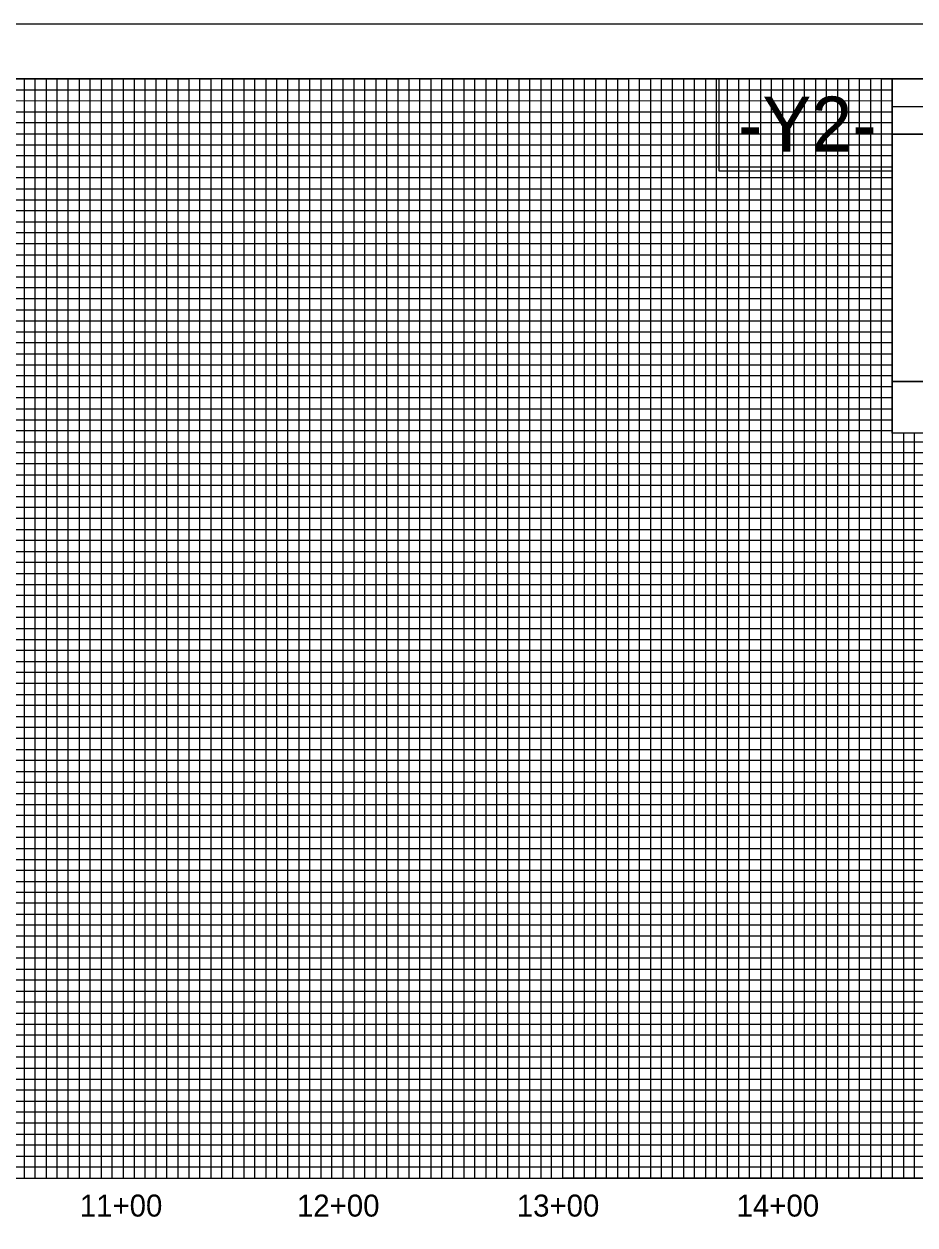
# Model space of a CAD drawing. Extents: x 505602 to 507705, y 483109 to 484209.
# Drawn here: x 506674 to 507079, y 483662 to 484209 of the extents above; entities that cross this region are included whole.
import ezdxf

# ---------------------------------------------------------------- set-up
doc = ezdxf.new("R2010")
doc.units = 0
for name, color, linetype in [('Exist Vertical Profile Vertical Axis Label', 7, 'Continuous'), ('Old_Level_1', 7, 'Continuous'), ('Prop Grid Mask', 7, 'Continuous'), ('Sheet Layout Profile Border Port 1', 7, 'Continuous'), ('Sheet Plot Border Outside CELL', 7, 'Continuous'), ('Sheet Profile CELL', 7, 'Continuous'), ('Sheet Profile Grid Major CELL', 7, 'Continuous'), ('Sheet Profile Grid Middle CELL', 7, 'Continuous'), ('Sheet Profile Grid Minor CELL', 7, 'Continuous'), ('Sheet Sticker Exception Certification CELL', 7, 'Continuous')]:
    doc.layers.add(name, color=color, linetype=linetype)

msp = doc.modelspace()

# ---------------------------------------------------------------- linework, layer by layer
at = {"layer": 'Prop Grid Mask'}
msp.add_lwpolyline([(507069.08, 484183.71), (506990.09, 484183.71), (506990.09, 484142), (507069.08, 484142)], close=True, dxfattribs=at)
at = {"layer": 'Sheet Layout Profile Border Port 1'}
msp.add_lwpolyline([(506619.08, 484183.71), (506619.08, 483683.71), (507219.08, 483683.96), (507219.08, 484022.66), (507069.08, 484022.66), (507069.03, 484183.71)], close=True, dxfattribs=at)
at = {"layer": 'Sheet Plot Border Outside CELL'}
msp.add_lwpolyline([(505602.08, 483108.71), (507286.08, 483108.71), (507286.08, 484208.71), (505602.08, 484208.71)], close=True, dxfattribs=at)
at = {"layer": 'Sheet Profile CELL'}
for p, q in [((507069.03, 484171.16), (507269.08, 484171.16)), ((505769.08, 483683.71), (507269.08, 483683.71))]:
    msp.add_line(p, q, dxfattribs=at)
for points in [[(507269.08, 484183.71), (505769.08, 484183.71), (505769.08, 483133.71), (507269.08, 483133.71)], [(507069.03, 484183.71), (507269.08, 484183.71), (507269.08, 484158.66), (507069.03, 484158.66)], [(507069.03, 484158.66), (507169.08, 484158.66), (507169.08, 484046.16), (507069.03, 484046.16)]]:
    msp.add_lwpolyline(points, close=True, dxfattribs=at)
at = {"layer": 'Sheet Profile Grid Major CELL'}
for points in [[(506669.08, 484183.71), (506719.08, 484183.71), (506719.08, 483683.71), (506769.08, 483683.71), (506769.08, 484183.71), (506819.08, 484183.71), (506819.08, 483683.71), (506869.08, 483683.71), (506869.08, 484183.71), (506919.08, 484183.71), (506919.08, 483683.71), (506969.08, 483683.71), (506969.08, 484183.71), (507019.08, 484183.71), (507019.08, 483683.71), (507069.08, 483683.71), (507069.08, 484183.71), (507095.38, 484183.71)], [(505769.08, 484133.71), (507069.08, 484133.71)], [(507069.08, 484083.71), (505769.08, 484083.71), (505769.08, 484033.71), (507069.08, 484033.71)], [(507269.08, 483983.71), (505769.08, 483983.71), (505769.08, 483933.71), (507269.08, 483933.71)], [(507269.08, 483883.71), (505769.08, 483883.71), (505769.08, 483833.71), (507269.08, 483833.71)], [(507269.08, 483783.71), (505769.08, 483783.71), (505769.08, 483783.71), (505769.08, 483733.71), (507269.08, 483733.71)]]:
    msp.add_lwpolyline(points, dxfattribs=at)
at = {"layer": 'Sheet Profile Grid Middle CELL'}
msp.add_line((505769.08, 484158.71), (507069.03, 484158.71), dxfattribs=at)
msp.add_line((505769.08, 484158.71), (507069.03, 484158.71), dxfattribs=at)
for points in [[(506644.08, 483683.71), (506694.08, 483683.71), (506694.08, 484183.71), (506744.08, 484183.71), (506744.08, 483683.71), (506794.08, 483683.71), (506794.08, 484183.71), (506844.08, 484183.71), (506844.08, 483683.71), (506894.08, 483683.71), (506894.08, 484183.71), (506944.08, 484183.71), (506944.08, 483683.71), (506994.08, 483683.71), (506994.08, 484183.71), (507044.08, 484183.71), (507044.08, 483683.71), (507094.08, 483683.71), (507094.08, 484022.66)], [(507069.08, 484108.71), (505769.08, 484108.71), (505769.08, 484058.71), (507069.08, 484058.71)], [(507269.08, 484008.71), (505769.08, 484008.71), (505769.08, 483958.71), (507094.08, 483958.71)], [(507269.08, 483908.71), (505769.08, 483908.71), (505769.08, 483858.71), (507269.08, 483858.71)], [(507269.08, 483808.71), (505769.08, 483808.71), (505769.08, 483758.71), (507269.08, 483758.71)], [(507269.08, 483708.71), (505769.08, 483708.71)]]:
    msp.add_lwpolyline(points, dxfattribs=at)
at = {"layer": 'Sheet Profile Grid Minor CELL'}
for p, q in [((505819.08, 484178.71), (507069.08, 484178.71)), ((507069.08, 484173.71), (505819.08, 484173.36)), ((505819.08, 484168.71), (507069.08, 484168.71)), ((507069.03, 484048.71), (505819.08, 484048.71)), ((507069.08, 484043.71), (505819.08, 484043.71)), ((507069.08, 484038.71), (505819.08, 484038.71)), ((505819.08, 484028.71), (507069.08, 484028.71)), ((507069.08, 484023.71), (505819.08, 484023.71)), ((505819.08, 484018.71), (507219.08, 484018.71)), ((507219.08, 483998.71), (505819.08, 483998.71)), ((505819.08, 483993.71), (507219.08, 483993.71)), ((507219.08, 483973.71), (505819.08, 483973.71)), ((505819.08, 483968.71), (507219.08, 483968.71)), ((507219.08, 483948.71), (505819.08, 483948.71)), ((505819.08, 483943.71), (507219.08, 483943.71)), ((507219.08, 483938.71), (505819.08, 483938.71)), ((505819.08, 483928.71), (507219.08, 483928.71)), ((507219.08, 483923.71), (505819.08, 483923.71)), ((505819.08, 483918.71), (507219.08, 483918.71)), ((507219.08, 483913.71), (505819.08, 483913.71)), ((505819.08, 483903.71), (507219.08, 483903.71)), ((507219.08, 483898.71), (505819.08, 483898.71)), ((505819.08, 483893.71), (507219.08, 483893.71)), ((507219.08, 483888.71), (505819.08, 483888.71)), ((505819.08, 483878.71), (507219.08, 483878.71)), ((507219.08, 483873.71), (505819.08, 483873.71)), ((505819.08, 483868.71), (507219.08, 483868.71)), ((507219.08, 483863.71), (505819.08, 483863.71)), ((505819.08, 483853.71), (507219.08, 483853.71)), ((507219.08, 483848.71), (505819.08, 483848.71)), ((505819.08, 483843.71), (507219.08, 483843.71)), ((507219.08, 483838.71), (505819.08, 483838.71)), ((505819.08, 483828.71), (507219.08, 483828.71)), ((507219.08, 483823.71), (505819.08, 483823.71)), ((505819.08, 483818.71), (507219.08, 483818.71)), ((507219.08, 483813.71), (505819.08, 483813.71)), ((505819.08, 483803.71), (507219.08, 483803.71)), ((507219.08, 483798.71), (505819.08, 483798.71)), ((507219.08, 483793.71), (505819.08, 483793.71)), ((507219.08, 483788.71), (505819.08, 483788.71)), ((505819.08, 483778.71), (507219.08, 483778.71)), ((507219.08, 483773.71), (505819.08, 483773.71)), ((505819.08, 483768.71), (507219.08, 483768.71)), ((507219.08, 483763.71), (505819.08, 483763.71)), ((505819.08, 483753.71), (507219.08, 483753.71)), ((507219.08, 483748.71), (505819.08, 483748.71)), ((505819.08, 483743.71), (507219.08, 483743.71)), ((507219.08, 483738.71), (505819.08, 483738.71)), ((505819.08, 483728.71), (507219.08, 483728.71)), ((507219.08, 483723.71), (505819.08, 483723.71)), ((505819.08, 483718.71), (507219.08, 483718.71)), ((507219.08, 483713.71), (505819.08, 483713.71)), ((505819.08, 483703.71), (507219.08, 483703.71)), ((507219.08, 483698.71), (505819.08, 483698.71)), ((505819.08, 483693.71), (507219.08, 483693.71))]:
    msp.add_line(p, q, dxfattribs=at)
for points in [[(506664.08, 484183.71), (506674.08, 484183.71), (506674.08, 483683.71), (506679.08, 483683.71), (506679.08, 484183.71), (506684.08, 484183.71), (506684.08, 483683.71), (506689.08, 483683.71), (506689.08, 484183.71), (506699.08, 484183.71), (506699.08, 483683.71), (506704.08, 483683.71), (506704.08, 484183.71), (506709.08, 484183.71), (506709.08, 483683.71), (506714.08, 483683.71), (506714.08, 484183.71), (506724.08, 484183.71), (506724.08, 483683.71), (506729.08, 483683.71), (506729.08, 484183.71), (506734.08, 484183.71), (506734.08, 483683.71), (506739.08, 483683.71), (506739.08, 484183.71), (506749.08, 484183.71), (506749.08, 483683.71), (506754.08, 483683.71), (506754.08, 484183.71), (506759.08, 484183.71), (506759.08, 483683.71), (506764.08, 483683.71), (506764.08, 484183.71), (506774.08, 484183.71), (506774.08, 483683.71), (506779.08, 483683.71), (506779.08, 484183.71), (506784.08, 484183.71), (506784.08, 483683.71), (506789.08, 483683.71), (506789.08, 484183.71), (506799.08, 484183.71), (506799.08, 483683.71), (506804.08, 483683.71), (506804.08, 484183.71), (506809.08, 484183.71), (506809.08, 483683.71), (506814.08, 483683.71), (506814.08, 484183.71), (506824.08, 484183.71), (506824.08, 483683.71), (506829.08, 483683.71), (506829.08, 484183.71), (506834.08, 484183.71), (506834.08, 483683.71), (506839.08, 483683.71), (506839.08, 484183.71), (506849.08, 484183.71), (506849.08, 483683.71), (506854.08, 483683.71), (506854.08, 484183.71), (506859.08, 484183.71), (506859.08, 483683.71), (506864.08, 483683.71), (506864.08, 484183.71), (506874.08, 484183.71), (506874.08, 483683.71), (506879.08, 483683.71), (506879.08, 484183.71), (506884.08, 484183.71), (506884.08, 483683.71), (506889.08, 483683.71), (506889.08, 484183.71), (506899.08, 484183.71), (506899.08, 483683.71), (506904.08, 483683.71), (506904.08, 484183.71), (506909.08, 484183.71), (506909.08, 483683.71), (506914.08, 483683.71), (506914.08, 484183.71), (506924.08, 484183.71), (506924.08, 483683.71), (506929.08, 483683.71), (506929.08, 484183.71), (506934.08, 484183.71), (506934.08, 483683.71), (506939.08, 483683.71), (506939.08, 484183.71), (506949.08, 484183.71), (506949.08, 483683.71), (506954.08, 483683.71), (506954.08, 484183.71), (506959.08, 484183.71), (506959.08, 483683.71)], [(506959.08, 483683.71), (506964.08, 483683.71), (506964.08, 484183.71), (506974.08, 484183.71), (506974.08, 483683.71), (506979.08, 483683.71), (506979.08, 484183.71), (506984.08, 484183.71), (506984.08, 483683.71), (506989.08, 483683.71), (506989.08, 484183.71), (506999.08, 484183.71), (506999.08, 483683.71), (507004.08, 483683.71), (507004.08, 484183.71), (507009.08, 484183.71), (507009.08, 483683.71), (507014.08, 483683.71), (507014.08, 484183.71), (507024.08, 484183.71), (507024.08, 483683.71), (507029.08, 483683.71), (507029.08, 484183.71), (507034.08, 484183.71), (507034.08, 483683.71), (507039.08, 483683.71), (507039.08, 484183.71), (507049.08, 484183.71), (507049.08, 483683.71), (507054.08, 483683.71), (507054.08, 484183.71), (507059.08, 484183.71), (507059.08, 483683.71), (507064.08, 483683.71), (507064.08, 484183.71), (507074.08, 484183.71)], [(507069.08, 484163.71), (505819.08, 484163.71), (505819.08, 484153.71), (507069.08, 484153.71)], [(507069.03, 484148.71), (505819.08, 484148.71), (505819.08, 484143.71), (507069.08, 484143.71)], [(507069.08, 484138.71), (505819.08, 484138.71), (505819.08, 484128.71), (507069.08, 484128.71)], [(507069.08, 484123.71), (505819.08, 484123.71), (505819.08, 484118.71), (507069.08, 484118.71)], [(507069.08, 484113.71), (505819.08, 484113.71), (505819.08, 484103.71), (507069.08, 484103.71)], [(507069.08, 484098.71), (505819.08, 484098.71), (505819.08, 484093.71), (507069.08, 484093.71)], [(507069.08, 484088.71), (505819.08, 484088.71), (505819.08, 484078.71), (507069.08, 484078.71)], [(507069.08, 484073.61), (505819.18, 484073.61), (505819.18, 484068.71), (507069.08, 484068.71)], [(507069.08, 484063.71), (505819.08, 484063.71), (505819.08, 484053.71), (507069.08, 484053.71)], [(507074.08, 484022.66), (507074.08, 483683.71), (507079.08, 483683.71), (507079.08, 484022.66)], [(507219.08, 484013.71), (505819.08, 484013.71), (505819.08, 484003.71), (507219.08, 484003.71)], [(507219.08, 483988.71), (505819.08, 483988.71), (505819.08, 483978.71), (507219.08, 483978.71)], [(507219.08, 483963.71), (505819.08, 483963.71), (505819.08, 483953.71), (507219.08, 483953.71)], [(507219.08, 483688.71), (505819.08, 483688.71)]]:
    msp.add_lwpolyline(points, dxfattribs=at)
at = {"layer": 'Sheet Sticker Exception Certification CELL'}
for p, q in [((507069.03, 484022.66), (507069.03, 484046.16)), ((507069.03, 484046.16), (507269.07, 484046.16)), ((507069.03, 484022.66), (507069.03, 484046.16)), ((507069.03, 484046.16), (507269.07, 484046.16)), ((507269.07, 484022.66), (507069.03, 484022.66)), ((507269.07, 484022.66), (507069.03, 484022.66))]:
    msp.add_line(p, q, dxfattribs=at)

# ---------------------------------------------------------------- texts
at = {"layer": 'Exist Vertical Profile Vertical Axis Label'}
for s, p in [('11+00', (506699.41, 483666.21)), ('12+00', (506798.21, 483666.21)), ('13+00', (506898.21, 483666.21)), ('14+00', (506998.21, 483666.21))]:
    msp.add_text(s, height=10, dxfattribs=at).set_placement(p)
at = {"layer": 'Old_Level_1'}
msp.add_text('-Y2-', height=25, dxfattribs=at).set_placement((506998.82, 484150.68))

doc.saveas('drawing.dxf')
